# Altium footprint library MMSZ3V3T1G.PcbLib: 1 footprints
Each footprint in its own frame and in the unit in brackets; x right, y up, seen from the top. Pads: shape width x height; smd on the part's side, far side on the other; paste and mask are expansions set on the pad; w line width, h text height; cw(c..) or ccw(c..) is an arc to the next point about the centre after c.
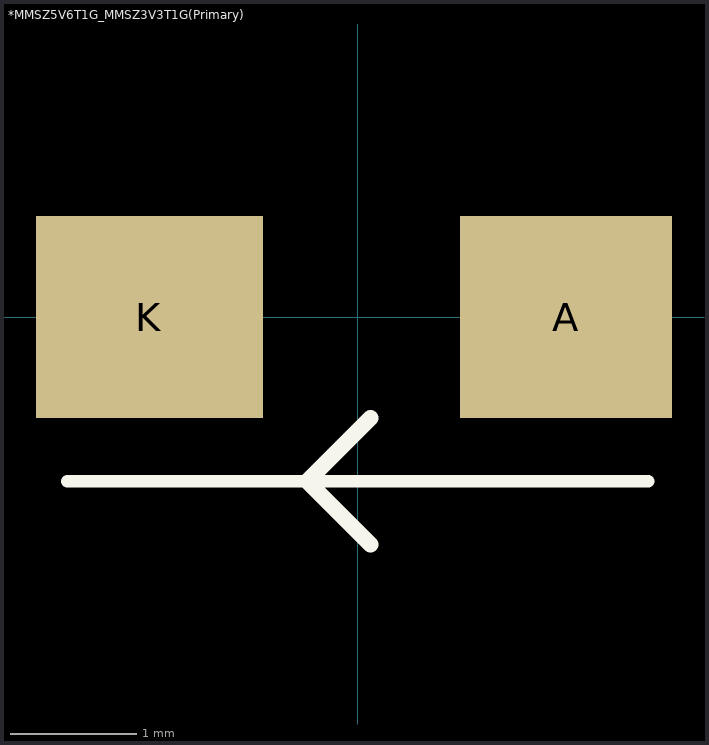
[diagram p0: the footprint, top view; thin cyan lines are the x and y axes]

## *MMSZ5V6T1G_MMSZ3V3T1G(Primary) [mm]
pads (2):
  rect 1.68x1.6 smd: A(1.65,0)
  rect 1.8x1.6 smd: K(-1.65,0)
Top Overlay:
  lines w0.1: -2.3,-1.3 -0.4,-1.3 2.3,-1.3
  lines w0.127: 0.1,-1.8 -0.4,-1.3 0.1,-0.8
